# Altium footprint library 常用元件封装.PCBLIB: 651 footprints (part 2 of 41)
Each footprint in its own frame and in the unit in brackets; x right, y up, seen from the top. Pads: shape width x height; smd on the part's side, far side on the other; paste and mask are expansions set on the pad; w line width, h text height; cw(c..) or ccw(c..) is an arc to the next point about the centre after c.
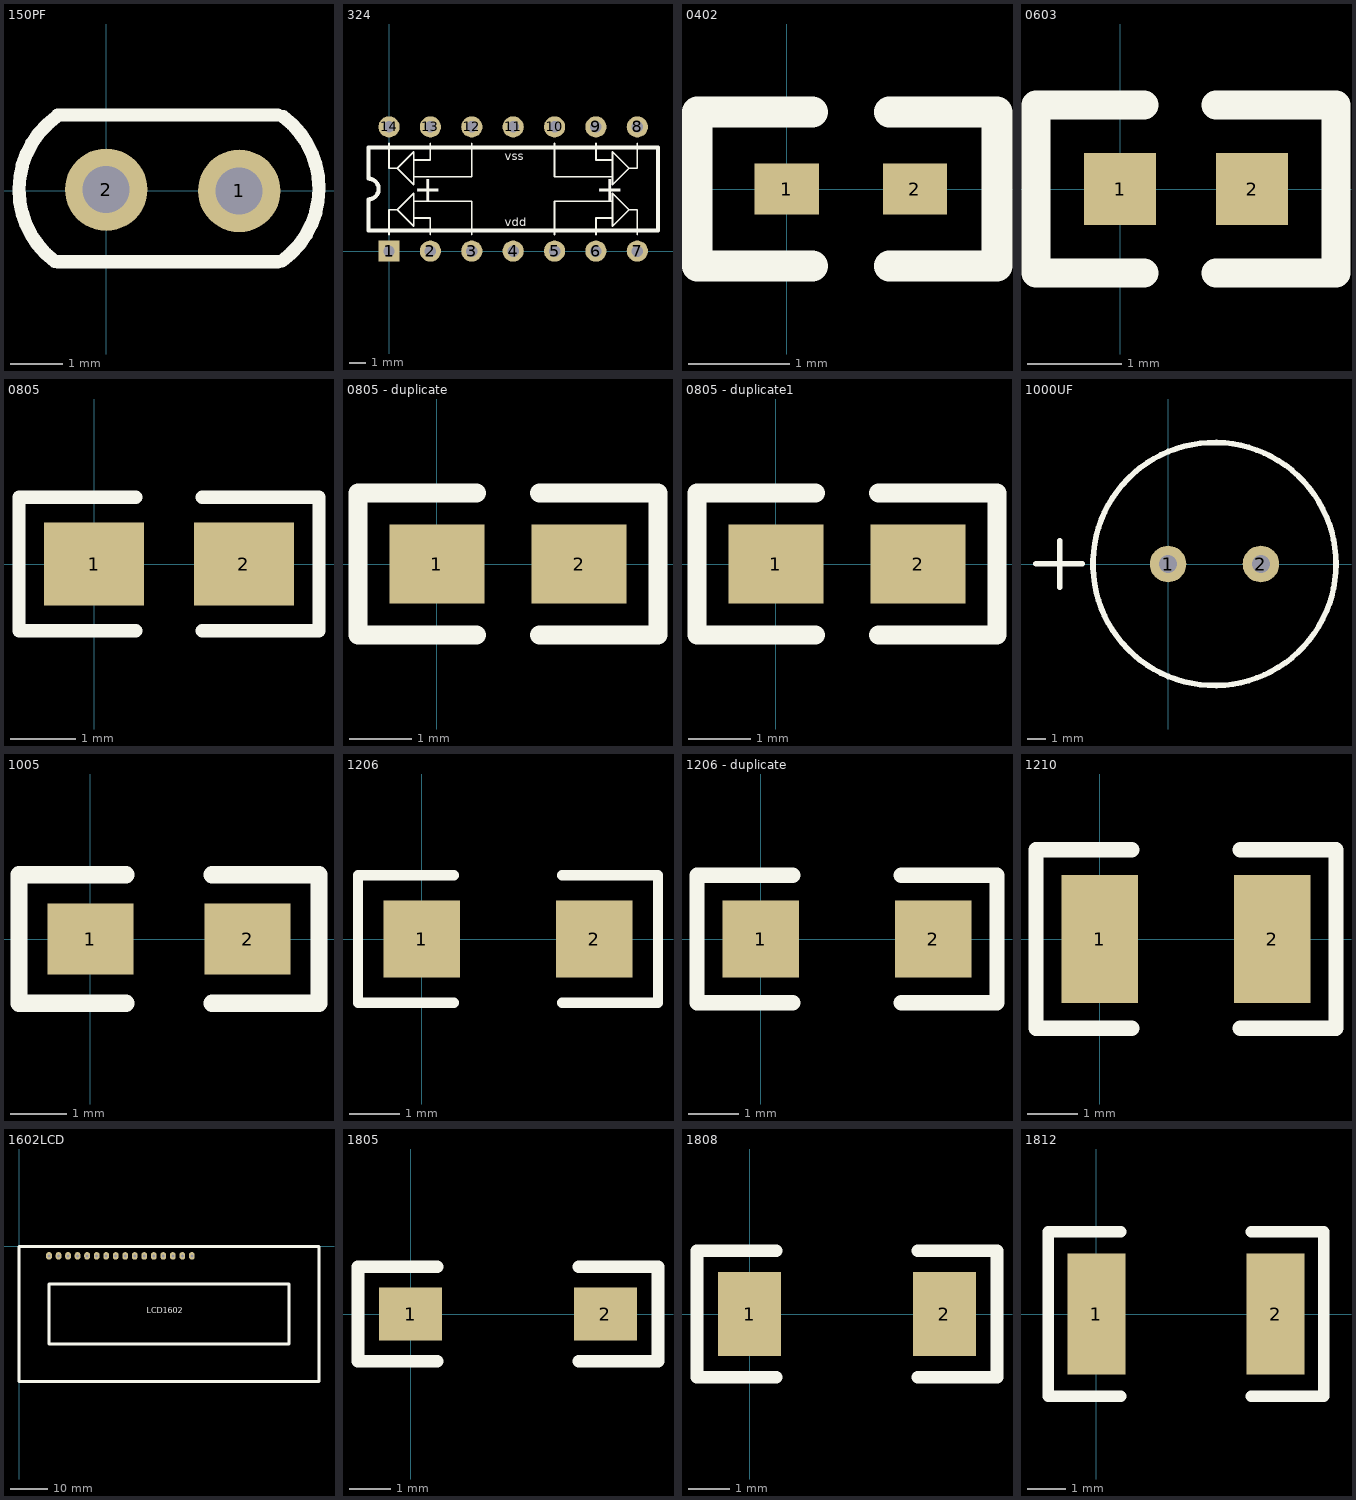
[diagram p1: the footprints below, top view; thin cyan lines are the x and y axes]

## 150PF [mil]
pads (2):
  round 62 hole 35.43: 1(100,0) 2(0,1)
TopOverlay:
  lines w10: -38.7,-52.9 cw(c1.97,1) -37.75,55.6 ; -36.42,-53.15 128.94,-53.15 ; -36.42,57.09 128.94,57.09 ; 132.24,-52.64 ccw(c92.52,1.95) 133.18,55.85

## 324 [mm]
pads (14):
  rect 1.3x1.3 hole 0.7: 1(0,0)
  round 1.3 hole 0.7: 2(2.54,0) 3(5.08,0) 4(7.62,0) 5(10.16,0) 6(12.7,0) 7(15.24,0) 8(15.24,7.62) 9(12.7,7.62) 10(10.16,7.62) 11(7.62,7.62) 12(5.08,7.62) 13(2.54,7.62) 14(0,7.62)
TopOverlay:
  lines w0.102: 0,1.016 0,2.54 0.508,2.54 ; 0,6.604 0,5.08 0.508,5.08 ; 1.524,2.032 2.54,2.032 2.54,1.016 ; 1.524,3.048 5.08,3.048 5.08,1.016 ; 1.524,4.572 5.08,4.572 5.08,6.604 ; 1.524,5.588 2.54,5.588 2.54,6.604 ; 10.16,1.016 10.16,3.048 13.716,3.048 ; 10.16,6.604 10.16,4.572 13.716,4.572 ; 12.7,1.016 12.7,2.032 13.716,2.032 ; 12.7,6.604 12.7,5.588 13.716,5.588 ; 15.24,1.016 15.24,2.54 14.732,2.54 ; 15.24,6.604 15.24,5.08 14.732,5.08 ; 0.508,2.54 1.524,1.524 1.524,3.556 0.508,2.54 ; 0.508,5.08 1.524,6.096 1.524,4.064 0.508,5.08 ; 14.732,2.54 13.716,1.524 13.716,3.556 14.732,2.54 ; 14.732,5.08 13.716,4.064 13.716,6.096 14.732,5.08
  lines w0.254: -1.27,1.27 16.51,1.27 16.51,6.35 -1.27,6.35 -1.27,4.445 cw(c-1.27,3.81) -1.27,3.175 -1.27,1.27
  text "+" at 12.7,3.048 h1.52
  text "+" at 1.524,3.048 h1.52
  text "vss" at 7.112,5.588 h0.51
  text "vdd" at 7.112,1.524 h0.51

## 0402 [mil]
pads (2):
  rect 25x20 smd: 1(0,0) 2(50,0)
TopOverlay:
  lines w12: 10,-30 -35,-30 -35,30 10,30 ; 40,-30 82,-30 82,30 40,30

## 0603 [mil]
pads (2):
  rect 30x30 smd: 1(0,0) 2(55,0)
TopOverlay:
  lines w12: 10,-35 -35,-35 -35,35 10,35 ; 40,-35 90,-35 90,35 40,35

## 0805 [mil]
pads (2):
  rect 60x50 smd: 1(0,0) 2(90,0)
TopOverlay:
  lines w8: 25,-40 -45,-40 -45,40 25,40 ; 65,-40 135,-40 135,40 65,40

## 0805 - duplicate [mil]
pads (2):
  rect 60x50 smd: 1(0,0) 2(90,0)
TopOverlay:
  lines w12: 25,-45 -50,-45 -50,45 25,45 ; 65,-45 140,-45 140,45 65,45

## 0805 - duplicate1 [mil] "1/8W"
pads (2):
  rect 60x50 smd: 1(0,0) 2(90,0)
TopOverlay:
  lines w12: 25,-45 -50,-45 -50,45 25,45 ; 65,-45 140,-45 140,45 65,45

## 1000UF [mm]
pads (2):
  round 2 hole 1: 1(0,0) 2(5.08,0)
TopOverlay:
  circle w0.305: c2.54,0 r6.65
  lines w0.305: -7.227,0.025 -4.687,0.025 ; -5.927,-1.27 -5.927,1.27

## 1005 [mil]
pads (2):
  rect 60x50 smd: 1(0,0) 2(110,0)
TopOverlay:
  lines w12: 25,-45 -50,-45 -50,45 25,45 ; 85,-45 160,-45 160,45 85,45

## 1206 [mil]
pads (2):
  rect 60x60 smd: 1(0,0) 2(135,0)
TopOverlay:
  lines w8: 25,-50 -50,-50 -50,50 25,50 ; 110,-50 185,-50 185,50 110,50

## 1206 - duplicate [mil] "1/4W 3.2X1.6"
pads (2):
  rect 60x60 smd: 1(0,0) 2(135,0)
TopOverlay:
  lines w12: 25,-50 -50,-50 -50,50 25,50 ; 110,-50 185,-50 185,50 110,50

## 1210 [mil]
pads (2):
  rect 60x100 smd: 1(0,0) 2(135,0)
TopOverlay:
  lines w12: 25,-70 -50,-70 -50,70 25,70 ; 110,-70 185,-70 185,70 110,70

## 1602LCD [mil] "LCD module 16*2 char"
pads (16):
  oval 60x80 hole 30: 1(314.96,-98.43) 2(414.96,-98.43) 3(514.96,-98.43) 4(614.96,-98.43) 5(714.96,-98.43) 6(814.96,-98.43) 7(914.96,-98.43) 8(1014.96,-98.43) 9(1114.96,-98.43) 10(1214.96,-98.43) 11(1314.96,-98.43) 12(1414.96,-98.43) 13(1514.96,-98.43) 14(1614.96,-98.43) 15(1714.96,-98.43) 16(1814.96,-98.43)
TopOverlay:
  lines w30: 0,-1417.32 3149.61,-1417.32 3149.61,0 0,0 0,-1417.32 ; 314.96,-1023.62 2834.65,-1023.62 2834.65,-393.7 314.96,-393.7 314.96,-1023.62
  text "LCD1602" at 1340,-700 h60

## 1805 [mil]
pads (2):
  rect 60x50 smd: 1(0,0) 2(185,0)
TopOverlay:
  lines w12: 25,-45 -50,-45 -50,45 25,45 ; 160,-45 235,-45 235,45 160,45

## 1808 [mil]
pads (2):
  rect 60x80 smd: 1(0,0) 2(185,0)
TopOverlay:
  lines w12: 25,-60 -50,-60 -50,60 25,60 ; 160,-60 235,-60 235,60 160,60

## 1812 [mil] "4.5X3.2"
pads (2):
  rect 60x125 smd: 1(0,0) 2(185,0)
TopOverlay:
  lines w12: 25,-85 -50,-85 -50,85 25,85 ; 160,-85 235,-85 235,85 160,85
